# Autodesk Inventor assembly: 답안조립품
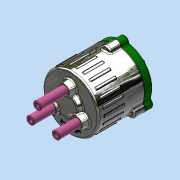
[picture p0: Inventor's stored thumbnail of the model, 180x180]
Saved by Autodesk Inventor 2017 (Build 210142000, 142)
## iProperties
Part Number: 답안조립품
Material: 일반
Document SubType Name: Assembly
Designer: MRC
Mass: 2354.47 g
Surface Area: 1884.92 cm^2
Volume: 517.816 cm^3
Density: 4.54692 g/cm^3
Author: MRC
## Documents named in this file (15)
- C:\Users\MRC\Desktop\620811V1002\답안조립품.iam
- C:\Users\MRC\Desktop\620811V1002\본체.ipt
- C:\Users\MRC\Desktop\620811V1002\가변스프링1.ipt
- C:\Users\MRC\Desktop\620811V1002\가변스프링2.ipt
- C:\Users\MRC\Desktop\620811V1002\가변스프링3.ipt
- C:\Users\MRC\Desktop\620811V1002\개스킷.ipt
- C:\Users\MRC\Desktop\620811V1002\멈춤링 10x1.ipt
- C:\Users\MRC\Desktop\620811V1002\멈춤링 22x1.2.ipt
- C:\Users\MRC\Desktop\620811V1002\메인 축.ipt
- C:\Users\MRC\Desktop\620811V1002\베어링 NA 4900.ipt
- C:\Users\MRC\Desktop\620811V1002\볼트 M5.ipt
- C:\Users\MRC\Desktop\620811V1002\슬라이드 축.ipt
- C:\Users\MRC\Desktop\620811V1002\오일 실.ipt
- C:\Users\MRC\Desktop\620811V1002\커버.ipt
- C:\Users\MRC\Desktop\620811V1002\판캠.ipt
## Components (4 placed, 4 different names)
1. 개스킷:1
2. 가변스프링1:1
3. 가변스프링2:1
4. 가변스프링3:1
